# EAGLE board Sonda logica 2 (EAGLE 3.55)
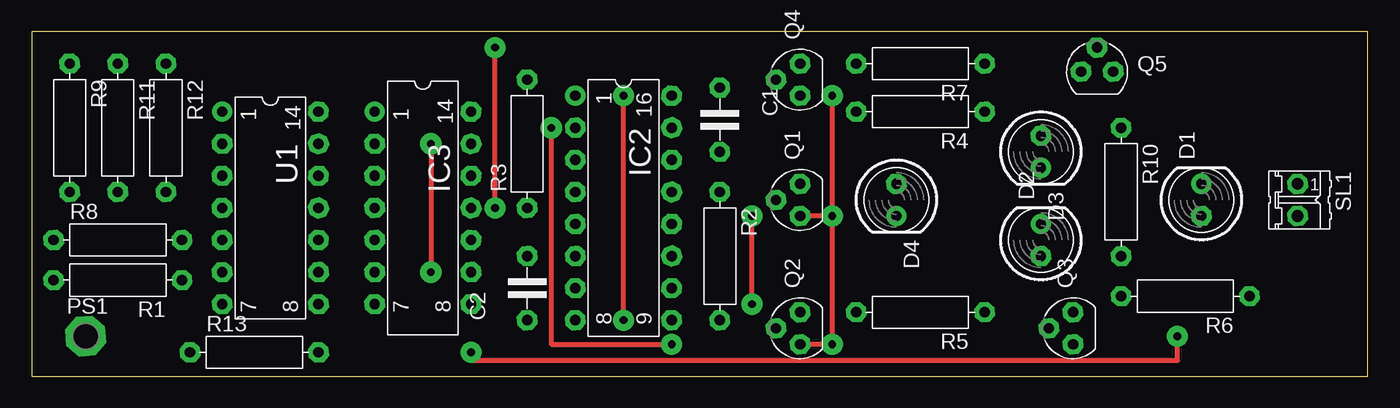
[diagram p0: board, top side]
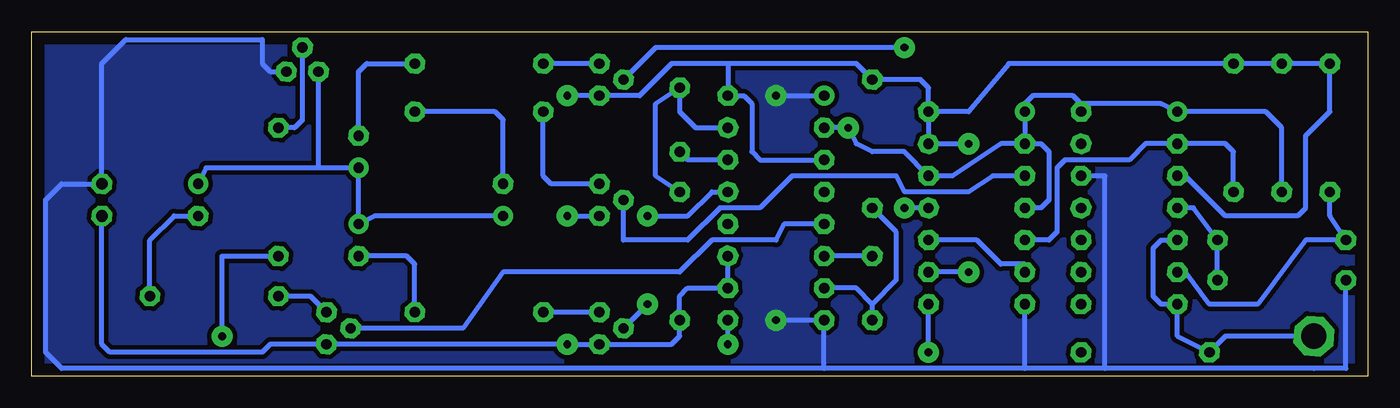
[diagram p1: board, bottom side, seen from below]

Size 105.72 x 27.3 mm. Coordinates in mm from the lower left corner, seen from the top.
Outline: 0,0 105.72,0 105.72,27.3 0,27.3 0,0
Copper layers used: Top, Bottom

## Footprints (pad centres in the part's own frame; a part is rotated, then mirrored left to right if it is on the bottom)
5 = drill 0.813 pad 1.6 octagon:  -2.54,0;  2.54,0
D5 = drill 0.813 pad 1.6 octagon:  -1.27,0 | drill 0.813 pad 1.6 round:  1.27,0
L16 = drill 0.813 pad 1.6 round:  -8.89,-3.81 | drill 0.813 pad 1.6 octagon:  -6.35,-3.81;  -3.81,-3.81;  -1.27,-3.81;  1.27,-3.81;  3.81,-3.81;  6.35,-3.81;  8.89,-3.81;  8.89,3.81;  6.35,3.81;  3.81,3.81;  1.27,3.81;  -1.27,3.81;  -3.81,3.81;  -6.35,3.81;  -8.89,3.81
L14 = drill 0.813 pad 1.6 round:  -7.62,-3.81 | drill 0.813 pad 1.6 octagon:  -5.08,-3.81;  -2.54,-3.81;  0,-3.81;  2.54,-3.81;  5.08,-3.81;  7.62,-3.81;  7.62,3.81;  5.08,3.81;  2.54,3.81;  0,3.81;  -2.54,3.81;  -5.08,3.81;  -7.62,3.81
-20 = drill 2.007 pad 3.15 octagon:  0,0
T54A = drill 0.813 pad 1.6 octagon:  -1.27,0;  0,1.905;  1.27,0
10 = drill 0.813 pad 1.6 octagon:  -5.08,0;  5.08,0
P = drill 0.914 pad 1.6 octagon:  -1.27,0;  1.27,0

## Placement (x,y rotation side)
C1  1uF  [5]  54.45,20.32 270 top
C2  1uF  [5]  39.2,6.98 90 top
D1  LED5  [D5]  92.55,13.96 90 top
D2  LED5  [D5]  79.84,10.79 90 top
D3  LED5  [D5]  79.84,17.78 270 top
D4  LED5  [D5]  68.42,13.96 270 top
IC2  74C123  [L16]  46.82,13.33 270 top
IC3  74C86  [L14]  30.95,13.33 270 top
PS1  P1-20  [-20]  4.28,3.17 0 top
Q1  BC547  [T54A]  60.79,13.96 90 top
Q2  BC547  [T54A]  60.79,3.8 90 top
Q3  BC547  [T54A]  82.39,3.8 90 top
Q4  BC547  [T54A]  60.79,23.49 90 top
Q5  BC547  [T54A]  84.29,24.12 0 top
R1  10K  [10]  6.82,7.61 180 top
R2  100K  [10]  54.45,9.52 270 top
R3  100K  [10]  39.2,18.41 90 top
R4  470  [10]  70.32,20.95 180 top
R5  470  [10]  70.32,5.08 180 top
R6  470  [10]  91.28,6.34 180 top
R7  470  [10]  70.32,24.76 180 top
R8  10K  [10]  6.82,10.79 0 top
R9  10K  [10]  3.01,19.68 270 top
R10  10K  [10]  86.2,14.6 270 top
R11  10K  [10]  6.82,19.68 270 top
R12  10K  [10]  10.63,19.68 270 top
R13  1M  [10]  17.62,1.9 0 top
SL1  M02  [P]  100.17,13.96 270 top
U1  LM339N  [L14]  18.89,13.33 270 top

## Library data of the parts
C1 C2 R1-R13 = discrete
D1-D4 = led
IC2 IC3 = 74xx
PS1 = testpad
Q1-Q5 = trans-sm
SL1 = conquick
U1 = linear

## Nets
GND: IC2. IC3. Q5. R1. R13. SL1. U1.
N$1: IC2. IC3. R11. U1.
N$2: Q1. R4.
N$3: R8. R9. U1.
N$4: D4. R4.
N$5: R1. R8. U1.
N$6: IC3. Q4.
N$7: IC2. Q2.
N$8: C1. IC2.
N$9: C1. IC2. R2.
N$10: IC2. Q3.
N$11: C2. IC2. R3.
N$12: C2. IC2.
N$13: Q3. R6.
N$15: Q2. R5.
N$16: D2. R5.
N$17: D1. R6.
N$18: IC3. R12. U1.
N$19: IC3. Q1.
N$20: Q4. R7.
N$21: D3. R7.
N$22: PS1. R13. U1.
N$23: IC3.
N$24: Q5. R10.
N$26: IC3. R10.
N$50: D1. D2. D3. D4. Q5.
VCC: IC2. IC3. Q1. Q2. Q3. Q4. R2. R3. R9. R11. R12. SL1. U1.

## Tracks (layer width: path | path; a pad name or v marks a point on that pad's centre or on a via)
GND  (via drill 0.61 pad 1.68)
  Top 0.406: v46.82,4.44 v46.82,22.22
  Bottom 0.406: 100.17,15.24 100.17,14.6 | Q5. 86.83,24.12 87.47,24.76 87.47,26.66 98.26,26.66 100.17,24.76 100.17,15.24 | 27.14,0.63 43.01,0.63 | 27.14,0.63 27.14,5.71 | 20.79,0.63 27.14,0.63 | 20.79,0.63 4.28,0.63 1.74,0.63 R1. | 100.17,15.24 103.34,15.24 104.61,13.96 104.61,1.9 103.34,0.63 43.01,0.63 | 43.01,0.63 43.01,4.44 v46.82,4.44 | 22.7,15.87 20.79,15.87 20.79,0.63 | v46.82,22.22 43.01,22.22
  pour Bottom (isolate 0.356): 0.47,26.66 0.47,1.26 1.1,0.63 105.25,0.63 105.25,26.66
N$1  (via drill 0.61 pad 1.68)
  Top 0.406: v41.11,19.68 41.11,2.54 v50.63,2.54
  Bottom 0.406: R11. 6.82,19.68 8.09,20.95 15.08,20.95 16.34,21.59 22.7,21.59 23.33,22.22 26.5,22.22 27.14,21.59 27.14,20.95 27.14,18.41 | v41.11,19.68 43.01,19.68 v41.11,19.68 | v41.11,19.68 40.47,18.41 39.2,17.78 36.66,17.78 34.76,15.87 32.85,15.87 29.05,18.41 27.14,18.41 | 27.14,13.33 25.87,13.33 25.23,13.96 25.23,17.78 25.87,18.41 27.14,18.41 | v50.63,2.54 50.63,4.44
N$2
  Bottom 0.406: R4. 65.24,15.87 64.61,15.24 Q1.
N$3
  Bottom 0.406: 15.08,8.25 14.44,8.25 12.54,5.71 8.72,5.71 4.92,10.79 1.74,10.79 3.01,12.7 R9.
N$4
  Bottom 0.406: 68.42,15.24 68.42,20.32 69.05,20.95 75.4,20.95
N$5
  Bottom 0.406: 11.9,7.61 R8. 13.8,13.33 15.08,13.33
N$6  (via drill 0.61 pad 1.68)
  Top 0.406: v36.66,13.33 v36.66,26.03
  Bottom 0.406: 58.89,23.49 56.35,26.03 v36.66,26.03 | 34.76,13.33 v36.66,13.33
N$7  (via drill 0.61 pad 1.68)
  Top 0.406: v56.98,5.71 v56.98,12.7
  Bottom 0.406: 58.89,3.8 v56.98,5.71 | v56.98,12.7 53.81,12.7 51.9,14.6 50.63,14.6
N$8
  Bottom 0.406: 50.63,17.14 53.81,17.14 C1.
N$9
  Bottom 0.406: 50.63,19.68 53.17,19.68 54.45,20.95 54.45,22.86 56.35,21.59 56.35,15.87 54.45,14.6
N$10
  Bottom 0.406: 42.38,12.06 43.01,12.06 46.19,12.06 46.82,10.79 51.9,10.79 54.45,8.25 68.42,8.25 71.59,3.8 80.48,3.8
N$11
  Bottom 0.406: 39.2,5.71 40.47,6.98 43.01,6.98 | 39.2,4.44 39.2,5.71 | 39.2,5.71 37.3,7.61 37.3,11.43 39.2,13.33
N$12
  Bottom 0.406: C2. 43.01,9.52
N$13
  Bottom 0.406: Q3. 83.66,6.34 R6.
N$15
  Bottom 0.406: Q2. R5.
N$16
  Bottom 0.406: 75.4,5.08 75.4,8.88 76.04,9.52 79.84,9.52
N$17
  Bottom 0.406: 92.55,12.7 94.45,12.7 96.36,10.79 96.36,6.34
N$18
  Bottom 0.406: R12. 10.63,17.78 11.27,18.41 15.08,18.41 17.62,18.41 18.89,17.14 23.96,17.14 24.6,16.5 24.6,11.43 25.23,10.79 27.14,10.79
N$19
  Bottom 0.406: 27.14,15.87 29.68,15.87 31.59,14.6 36.66,14.6 37.3,15.87 45.55,15.87 48.09,13.33 51.27,13.33 53.81,10.79 58.89,10.79 58.89,13.96
N$20
  Bottom 0.406: Q4. R7.
N$21
  Bottom 0.406: 79.84,19.05 79.84,24.12 79.21,24.76 75.4,24.76
N$22
  Bottom 0.406: PS1. 11.27,3.17 12.54,1.9 15.08,3.17 15.08,5.71 16.34,5.71 16.98,6.34 16.98,10.16 16.34,10.79 15.08,10.79
N$23
  Bottom 0.406: 27.14,8.25 27.14,8.88 29.05,8.88 30.95,10.79 34.76,10.79
N$24
  Bottom 0.406: 84.29,26.03 84.29,20.32 84.92,19.68 86.2,19.68
N$26  (via drill 0.61 pad 1.68)
  Top 0.406: v34.76,1.9 34.76,1.26 90.64,1.26 v90.64,3.17
  Bottom 0.406: 34.76,6.34 34.76,5.71 v34.76,1.9 | v90.64,3.17 90.64,9.52 R10.
N$50
  Bottom 0.406: D4. 78.58,12.7 D2. D3. 83.02,16.5 | D1. 91.91,16.5 83.02,16.5 | 83.02,16.5 83.02,24.12
VCC  (via drill 0.61 pad 1.68)
  Top 0.406: v31.59,18.41 v31.59,8.25 | 60.79,2.54 v63.33,2.54 v63.33,12.7 | v63.33,12.7 60.79,12.7 | v63.33,22.22 v63.33,12.7
  Bottom 0.406: SL1. 100.17,2.54 99.53,1.9 87.47,1.9 86.83,2.54 82.39,2.54 v63.33,2.54 60.79,2.54 55.08,2.54 54.45,3.17 R2. 54.45,6.34 53.81,6.98 50.63,6.98 50.63,9.52 | 50.63,24.76 55.08,24.76 57.62,22.22 60.79,22.22 v63.33,22.22 | IC3. 31.59,20.95 28.41,24.76 10.63,24.76 6.82,24.76 3.01,24.76 3.01,20.95 4.92,19.05 4.92,13.33 5.55,12.7 11.27,12.7 14.44,15.87 15.08,15.87 | 50.63,24.76 IC2. 49.36,22.22 48.73,21.59 48.73,17.78 48.09,17.14 43.01,17.14 | 50.63,24.76 40.47,24.76 R3. 35.39,23.49 34.76,22.86 IC3. | IC3. 34.76,18.41 v31.59,18.41 | v31.59,8.25 34.76,8.25 | v63.33,12.7 60.79,12.7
